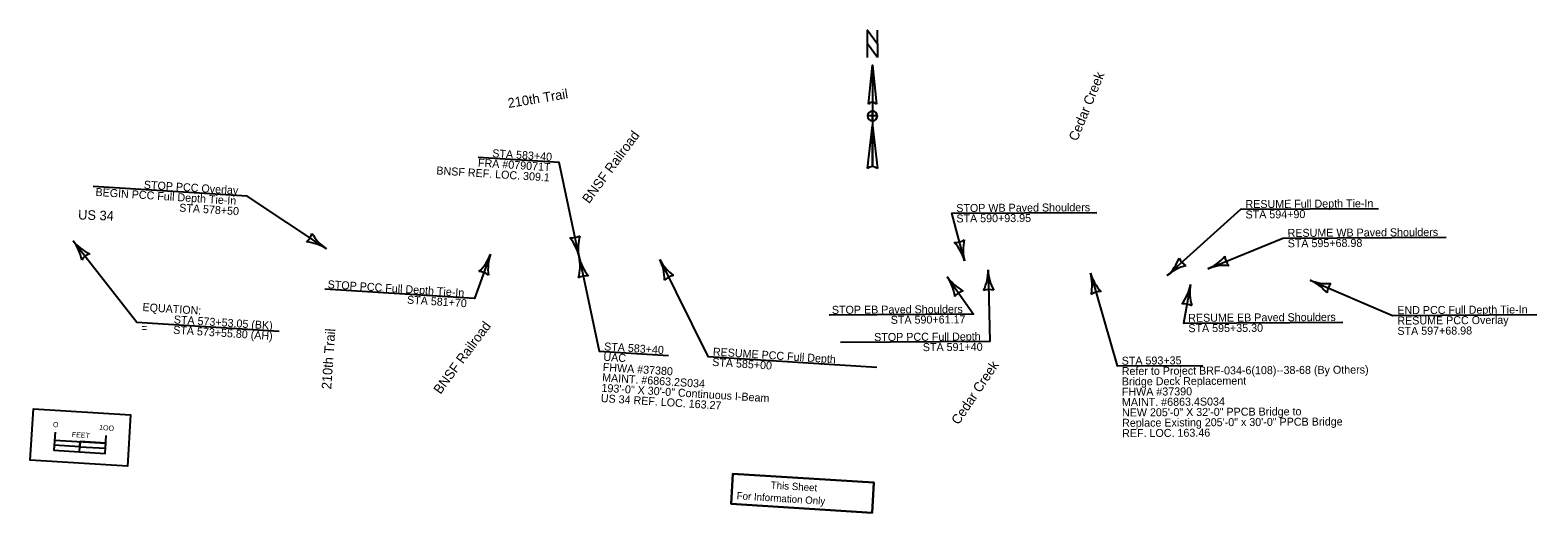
# Model space of a CAD drawing. Extents: x 22712865 to 22760106, y 6235088 to 6238602.
# Drawn here: x 22734893 to 22737830, y 6235088 to 6236030 of the extents above; entities that cross this region are included whole.
import ezdxf

# ---------------------------------------------------------------- set-up
doc = ezdxf.new("R2010")
doc.units = 0
for name, color, linetype in [('_CIVIL_CONSTRUCTION', 7, 'Continuous'), ('Contours Major', 7, 'Continuous'), ('Default', 7, 'Continuous'), ('Draft_3', 7, 'Continuous'), ('dsnTextOdd', 7, 'Continuous'), ('Entrance', 7, 'Continuous')]:
    doc.layers.add(name, color=color, linetype=linetype)

msp = doc.modelspace()

# ---------------------------------------------------------------- linework, layer by layer
at = {"layer": '_CIVIL_CONSTRUCTION'}
msp.add_line((22734989.7, 6235207.2), (22734990.9, 6235227.1), dxfattribs=at)
msp.add_line((22734989.7, 6235207.2), (22734990.9, 6235227.1), dxfattribs=at)
for points in [[(22734899.8, 6235291), (22735089.4, 6235279.1), (22735083.1, 6235179.2), (22734893.5, 6235191.2)], [(22734893.5, 6235191.2), (22734899.8, 6235291), (22735089.4, 6235279.1), (22735083.1, 6235179.2)], [(22734939.8, 6235210.3), (22734989.7, 6235207.2), (22734990.3, 6235217.2), (22734940.4, 6235220.4)], [(22734990.3, 6235217.2), (22735040.2, 6235214.1), (22735040.8, 6235224), (22734990.9, 6235227.1)]]:
    msp.add_lwpolyline(points, close=True, dxfattribs=at)
for points in [[(22734942, 6235245.3), (22734939.8, 6235210.3), (22735039.6, 6235204), (22735041.8, 6235239)], [(22734941, 6235230.3), (22735040.8, 6235224)]]:
    msp.add_lwpolyline(points, dxfattribs=at)
at = {"layer": 'Contours Major'}
msp.add_lwpolyline([(22734977.1, 6235619), (22735101.7, 6235460), (22735378.7, 6235442.5)], dxfattribs=at)
for centre, radius, start, end in [((22734910.2, 6235566.6), 85, 10.0059, 38.0783), ((22735044, 6235671.4), 85, 218.0783, 246.1508), ((22735021.1, 6235562.9), 32.8, 110.345, 145.8117)]:
    msp.add_arc(centre, radius, start, end, dxfattribs=at)
at = {"layer": 'Draft_3'}
for points in [[(22735963.4, 6235587.5), (22735924.3, 6235771.5), (22735767, 6235781.5)], [(22735471, 6235603.2), (22735316.6, 6235705.7), (22735016.4, 6235724.7)], [(22737109.8, 6235550.9), (22737253.2, 6235680.3), (22737521.2, 6235682)], [(22737188.7, 6235564.4), (22737335.3, 6235623.9), (22737653.4, 6235625.9)], [(22735790.9, 6235593), (22735759.4, 6235506), (22735468, 6235524.4)], [(22735963.4, 6235587.5), (22736002.6, 6235403.5), (22736137.8, 6235394.9)], [(22736960.1, 6235555.7), (22737011.9, 6235374.8), (22737179.3, 6235375.8)], [(22737388, 6235542), (22737549.1, 6235473.2), (22737830.2, 6235475)], [(22737155, 6235533.4), (22737141.6, 6235458.4), (22737452.3, 6235460.3)]]:
    msp.add_lwpolyline(points, dxfattribs=at)
for centre, radius, start, end in [((22735411.1, 6235641.8), 32.8, 309.4704, 344.9371), ((22735517.1, 6235674.7), 85, 209.1313, 237.2038), ((22735948.6, 6235657.2), 32.8, 264.2745, 299.7412), ((22735880.3, 6235569.8), 85, 12.0079, 40.0803), ((22736046.6, 6235605.2), 85, 163.9354, 192.0079), ((22735425, 6235531.8), 85, 57.2038, 85.2763), ((22735710.9, 6235621.9), 85, 312.0401, 340.1126), ((22735870.8, 6235564.1), 85, 160.1126, 188.1851), ((22735880.3, 6235569.8), 85, 343.9354, 12.0079), ((22736046.6, 6235605.2), 85, 192.0079, 220.0803), ((22737052.9, 6235614), 85, 312.0682, 340.1407), ((22737166.8, 6235487.8), 85, 103.9957, 132.0682), ((22737162.7, 6235598.6), 32.8, 204.3349, 239.8016), ((22737156.7, 6235643.1), 85, 292.0859, 320.1584), ((22737220.6, 6235485.6), 85, 84.0135, 112.0859), ((22737254.7, 6235591.2), 32.8, 184.3526, 219.8193), ((22735766.6, 6235526), 32.8, 52.3793, 87.846), ((22735978.2, 6235517.8), 32.8, 84.2745, 119.7412), ((22736878.4, 6235532.3), 85, 347.9106, 15.9831), ((22737041.8, 6235579.1), 85, 195.9831, 224.0556), ((22737354.7, 6235463.8), 85, 38.7976, 66.8701), ((22737421.4, 6235620.2), 85, 246.8701, 274.9426), ((22737453.6, 6235514), 32.8, 139.1368, 174.6035), ((22736979.7, 6235487.1), 32.8, 88.2497, 123.7164), ((22737071.3, 6235548.3), 85, 321.8591, 349.9316), ((22737238.7, 6235518.6), 85, 169.9316, 198.0041), ((22737142.5, 6235463.2), 32.8, 62.1983, 97.665)]:
    msp.add_arc(centre, radius, start, end, dxfattribs=at)
at = {"layer": 'dsnTextOdd'}
for points in [[(22736714.9, 6235579.5), (22736689.6, 6235672.4), (22736972.8, 6235674.2)], [(22736681.1, 6235548.6), (22736732, 6235475.7), (22736450.7, 6235474.1)], [(22736760.7, 6235562), (22736764.1, 6235422.3), (22736472.7, 6235420.5)]]:
    msp.add_lwpolyline(points, dxfattribs=at)
for centre, radius, start, end in [((22736696.1, 6235648.3), 32.8, 267.5212, 302.9879), ((22736632.9, 6235557.1), 85, 15.2546, 43.327), ((22736796.9, 6235601.9), 85, 167.1821, 195.2546), ((22736750.8, 6235597.2), 85, 214.9361, 243.0086), ((22736611.4, 6235499.9), 85, 6.8636, 34.9361), ((22736675.8, 6235560), 85, 333.2874, 1.3599), ((22736845.7, 6235564), 85, 181.3599, 209.4324), ((22736721.9, 6235490.1), 32.8, 107.2027, 142.6694), ((22736762.4, 6235490.8), 32.8, 73.6265, 109.0932)]:
    msp.add_arc(centre, radius, start, end, dxfattribs=at)
at = {"layer": 'Entrance'}
for p, q in [((22736535.2, 6235961.3), (22736542.8, 6235885.2)), ((22736535.2, 6235961.3), (22736535.2, 6235763.5)), ((22736527.9, 6235885.9), (22736529.3, 6235887.5)), ((22736527.6, 6235885.2), (22736527.6, 6235885.2)), ((22736525.7, 6235759.7), (22736535.2, 6235843.4)), ((22736535.2, 6235852.9), (22736535.2, 6235852.9))]:
    msp.add_line(p, q, dxfattribs=at)
for points in [[(22736544.7, 6235976.5), (22736525.7, 6236003.1), (22736525.7, 6236029.7), (22736544.7, 6236003.1)], [(22736259.5, 6235105.5), (22736534.5, 6235088.2), (22736538.2, 6235147.1), (22736263.2, 6235164.5)], [(22736263.2, 6235164.5), (22736538.2, 6235147.1), (22736534.5, 6235088.2), (22736259.5, 6235105.5)]]:
    msp.add_lwpolyline(points, close=True, dxfattribs=at)
for points in [[(22736525.7, 6235976.5), (22736525.7, 6236029.7), (22736544.7, 6236003.1), (22736544.7, 6236029.7)], [(22736527.6, 6235885.2), (22736535.2, 6235961.3), (22736535.2, 6235889)], [(22736535.2, 6235852.9), (22736535.2, 6235862.4), (22736525.7, 6235862.4)], [(22736544.7, 6235862.4), (22736535.2, 6235862.4), (22736535.2, 6235871.9)], [(22736535.2, 6235763.5), (22736535.2, 6235843.4), (22736544.7, 6235759.7)], [(22736120.7, 6235582.5), (22736214.6, 6235393.3), (22736543.5, 6235372.6)]]:
    msp.add_lwpolyline(points, dxfattribs=at)
for centre, radius, start, end in [((22736535.2, 6235879.5), 9.51, 90.0204, 143.1257), ((22736535.2, 6235879.5), 9.5, 36.8481, 90.0218), ((22736535.2, 6235862.4), 9.51, 90, 180), ((22736535.2, 6235862.4), 9.51, 180, 270), ((22736535.2, 6235862.4), 9.51, 0, 90), ((22736535.2, 6235862.4), 9.51, 270, 360), ((22736535.2, 6235749.8), 13.8, 89.9894, 133.619), ((22736535.2, 6235749.7), 13.8, 46.4021, 90.0006), ((22736196.9, 6235620.3), 85, 206.3947, 234.4672), ((22736044.6, 6235544.7), 85, 358.3222, 26.3947), ((22736152.4, 6235518.6), 32.8, 98.6614, 134.1281)]:
    msp.add_arc(centre, radius, start, end, dxfattribs=at)

# ---------------------------------------------------------------- texts
at = {"layer": '_CIVIL_CONSTRUCTION'}
for s, p in [('O', (22734937.7, 6235255.6)), ('O', (22734937.7, 6235255.6)), ('FEET', (22734974.5, 6235236.2)), ('1OO', (22735027.6, 6235249.9)), ('1OO', (22735027.6, 6235249.9))]:
    msp.add_text(s, height=10, rotation=356.3895, dxfattribs=at).set_placement(p)
at = {"layer": 'Contours Major'}
for s, height, p in [('EQUATION:', 15.6, (22735112.1, 6235481.9)), ('=', 15.6, (22735109.6, 6235441.6)), ('STA 573+55.80 (AH)', 15.601, (22735171.9, 6235437.6)), ('STA 573+53.05 (BK)', 15.601, (22735173.1, 6235457.8))]:
    msp.add_text(s, height=height, rotation=356.3895, dxfattribs=at).set_placement(p)
at = {"layer": 'Default'}
for s, rotation, p in [('Cedar Creek', 67.8583, (22736934.3, 6235812)), ('210th Trail', 9.2876, (22735826, 6235877.8)), ('BNSF Railroad', 53.4823, (22735982.9, 6235690.1)), ('US 34', 357.8939, (22734986.7, 6235660.6)), ('BNSF Railroad', 53.4823, (22735693.1, 6235318.3)), ('210th Trail', 86.0504, (22735480.2, 6235328.7)), ('Cedar Creek', 56.0323, (22736703, 6235258.7))]:
    msp.add_text(s, height=18.75, rotation=rotation, dxfattribs=at).set_placement(p)
at = {"layer": 'Draft_3'}
for s, height, rotation, p in [('FRA #079071T', 15.601, 356.3895, (22735766, 6235763.5)), ('STA 583+40', 15.6, 356.3895, (22735793.9, 6235782)), ('BNSF REF. LOC. 309.1', 15.601, 356.3895, (22735684.9, 6235748.4)), ('BEGIN PCC Full Depth Tie-In', 15.601, 356.3895, (22735020.5, 6235706.4)), ('STOP PCC Overlay', 15.601, 356.3895, (22735114.7, 6235720.7)), ('STA 578+50', 15.6, 356.3895, (22735183.7, 6235675.9)), ('RESUME Full Depth Tie-In', 15.601, 0.3647, (22737262.3, 6235682.6)), ('STA 594+90', 15.6, 0.3647, (22737262.4, 6235662.4)), ('RESUME WB Paved Shoulders', 15.601, 0.3647, (22737344.4, 6235626.3)), ('STA 595+68.98', 15.601, 0.3647, (22737344.5, 6235606.1)), ('STOP PCC Full Depth Tie-In', 15.601, 356.3895, (22735473, 6235526.4)), ('STA 581+70', 15.6, 356.3895, (22735627.7, 6235496.4)), ('RESUME EB Paved Shoulders', 15.601, 0.3647, (22737150.7, 6235460.7)), ('END PCC Full Depth Tie-In', 15.601, 0.3647, (22737558.2, 6235475.6)), ('STA 595+35.30', 15.601, 0.3647, (22737150.9, 6235440.5)), ('STA 597+68.98', 15.601, 0.3647, (22737558.4, 6235435.2)), ('RESUME PCC Overlay', 15.601, 0.3647, (22737558.3, 6235455.4)), ('STA 583+40', 15.6, 356.3895, (22736011.8, 6235405.2)), ('UAC', 15.6, 356.3895, (22736010.5, 6235385)), ('STA 593+35', 15.6, 0.3647, (22737021, 6235377.1)), ('MAINT. #6863.2S034', 15.601, 356.3895, (22736008, 6235344.7)), ('FHWA #37380', 15.601, 356.3895, (22736009.2, 6235364.9)), ('Refer to Project BRF-034-6(108)--38-68 (By Others)', 15.601, 0.3647, (22737021.1, 6235356.9)), ('193\'-0" X 30\'-0" Continuous I-Beam ', 15.601, 356.3895, (22736006.7, 6235324.6)), ('Bridge Deck Replacement', 15.601, 0.3647, (22737021.3, 6235336.7)), ('FHWA #37390', 15.601, 0.3647, (22737021.4, 6235316.6)), ('US 34 REF. LOC. 163.27', 15.601, 356.3895, (22736005.4, 6235304.4)), ('MAINT. #6863.4S034', 15.601, 0.3647, (22737021.5, 6235296.4)), ('NEW 205\'-0" X 32\'-0" PPCB Bridge to', 15.601, 0.3647, (22737021.6, 6235276.2)), ('Replace Existing 205\'-0" x 30\'-0" PPCB Bridge', 15.601, 0.3647, (22737021.8, 6235256)), ('REF. LOC. 163.46', 15.601, 0.3647, (22737021.9, 6235235.8))]:
    msp.add_text(s, height=height, rotation=rotation, dxfattribs=at).set_placement(p)
at = {"layer": 'dsnTextOdd'}
for s, height, p in [('STOP WB Paved Shoulders', 15.601, (22736698.6, 6235674.8)), ('STA 590+93.95', 15.601, (22736698.8, 6235654.6)), ('STOP EB Paved Shoulders', 15.601, (22736456.2, 6235476.3)), ('STA 590+61.17', 15.601, (22736570.9, 6235456.9)), ('STOP PCC Full Depth', 15.601, (22736538.6, 6235423.2)), ('STA 591+40', 15.6, (22736633.4, 6235403.6))]:
    msp.add_text(s, height=height, rotation=0.3647, dxfattribs=at).set_placement(p)
at = {"layer": 'Entrance'}
for s, height, p in [('STA 585+00', 15.6, (22736222.5, 6235374.9)), ('RESUME PCC Full Depth', 15.601, (22736223.8, 6235395)), ('For Information Only', 14.175, (22736270.2, 6235114.9)), ('This Sheet', 14.17, (22736336.6, 6235135.6))]:
    msp.add_text(s, height=height, rotation=356.3895, dxfattribs=at).set_placement(p)

doc.saveas('drawing.dxf')
